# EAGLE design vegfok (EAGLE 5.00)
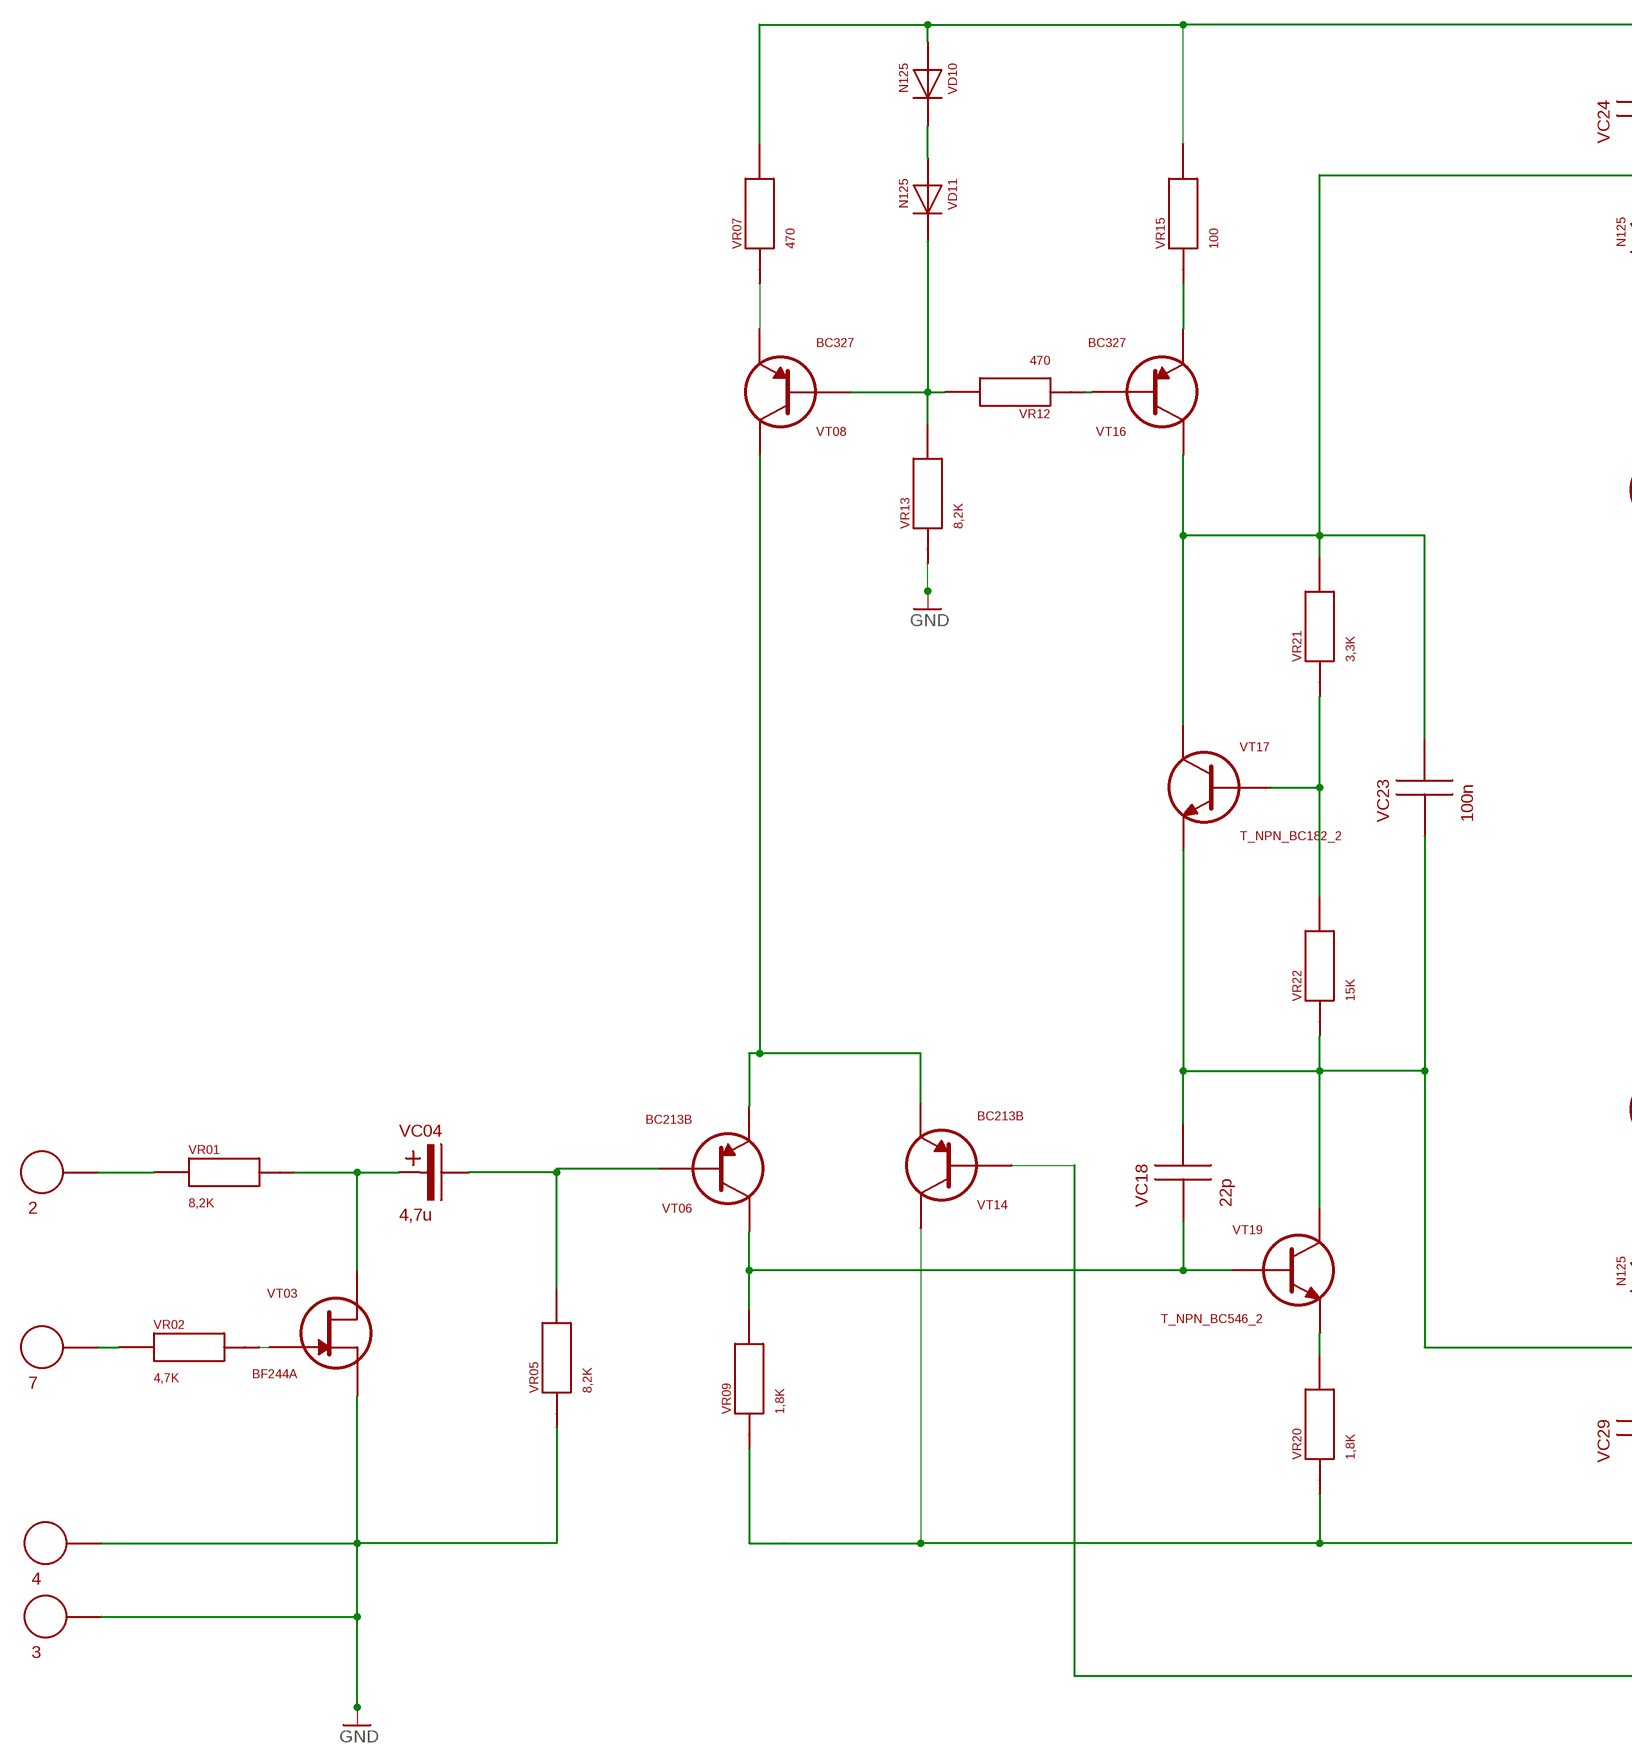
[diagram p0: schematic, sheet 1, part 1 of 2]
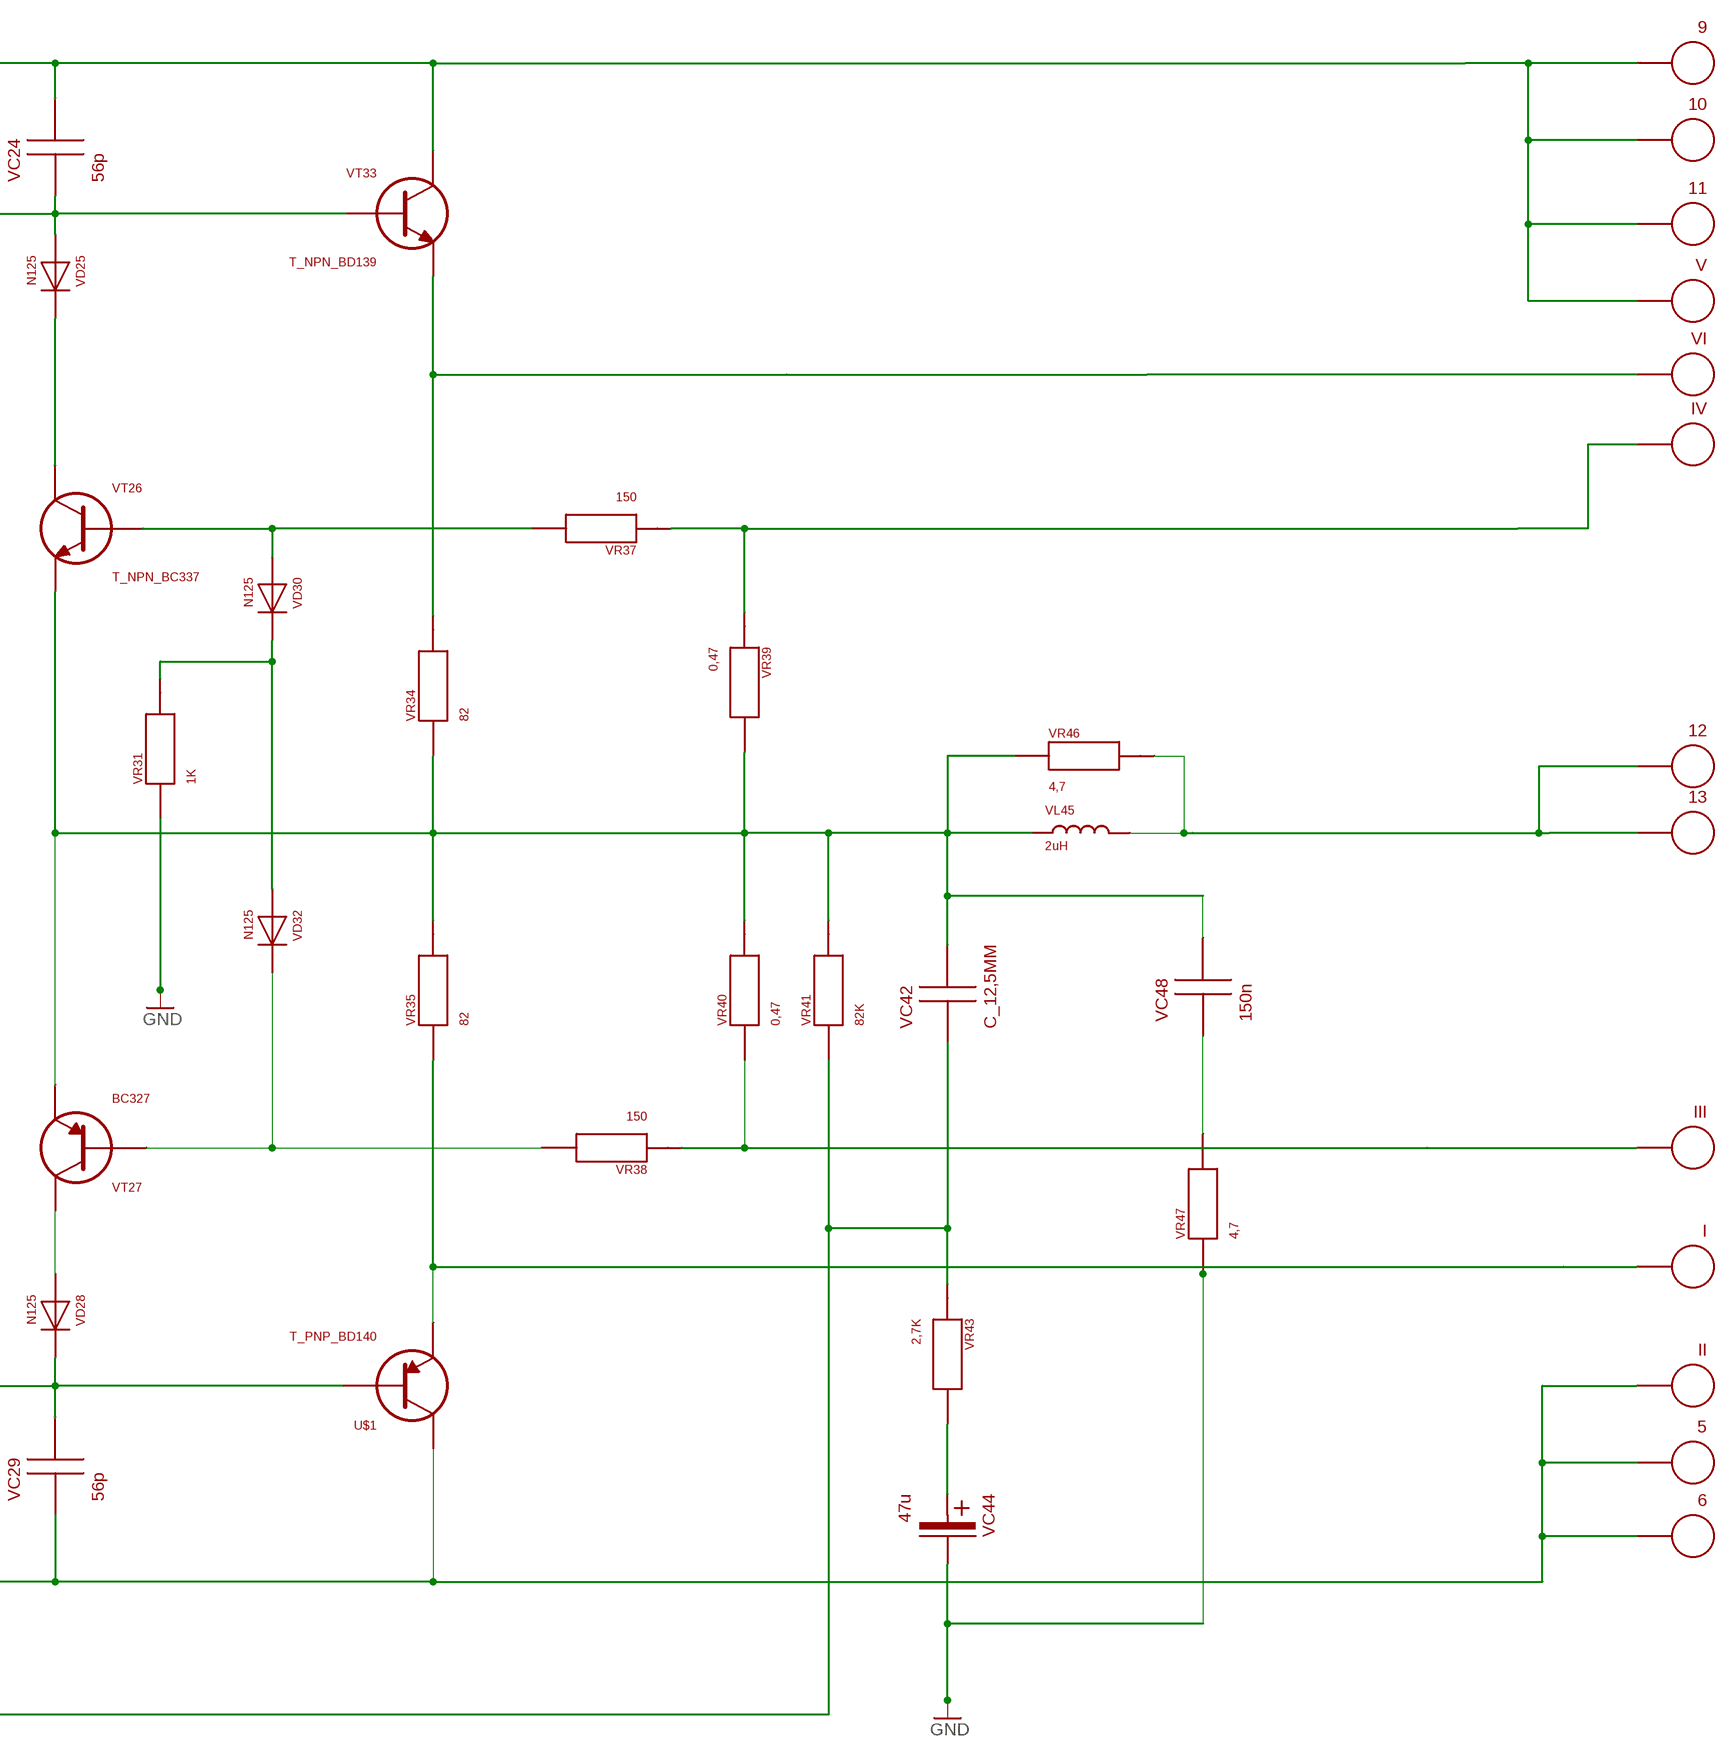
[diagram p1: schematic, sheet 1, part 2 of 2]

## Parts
2  WIREPAD_3-1,2MM  [WIREPAD_3-1,2]
3  WIREPAD_3-1,2MM  [WIREPAD_3-1,2]
4  WIREPAD_3-1,2MM  [WIREPAD_3-1,2]
5  WIREPAD_3-1,2MM  [WIREPAD_3-1,2]
6  WIREPAD_3-1,2MM  [WIREPAD_3-1,2]
7  WIREPAD_3-1,2MM  [WIREPAD_3-1,2]
9  WIREPAD_3-1,2MM  [WIREPAD_3-1,2]
10  WIREPAD_3-1,2MM  [WIREPAD_3-1,2]
11  WIREPAD_3-1,2MM  [WIREPAD_3-1,2]
12  WIREPAD_3-1,2MM  [WIREPAD_3-1,2]
13  WIREPAD_3-1,2MM  [WIREPAD_3-1,2]
I  WIREPAD_3-1,2MM  [WIREPAD_3-1,2]
II  WIREPAD_3-1,2MM  [WIREPAD_3-1,2]
III  WIREPAD_3-1,2MM  [WIREPAD_3-1,2]
IV  WIREPAD_3-1,2MM  [WIREPAD_3-1,2]
U$1  T_PNP_BD140  [TO126]
V  WIREPAD_3-1,2MM  [WIREPAD_3-1,2]
VC04  4,7u  CPOL_17,5MM  [CPOL_17,5]
VC18  22p  C_15MM  [C_15]
VC23  100n  C_15MM  [C_15]
VC24  56p  C_12,5MM  [C_12,5]
VC29  56p  C_15MM  [C_15]
VC42  C_12,5MM  [C_12,5]
VC44  47u  CPOL_22,5MM  [CPOL_22,5]
VC48  150n  C_17,5MM  [C_17,5]
VD10  N125  D_  [D_12,5]
VD11  N125  D_  [D_12,5]
VD25  N125  D_  [D_12,5]
VD28  N125  D_  [D_12,5]
VD30  N125  D_  [D_12,5]
VD32  N125  D_  [D_12,5]
VI  WIREPAD_3-1,2MM  [WIREPAD_3-1,2]
VL45  2uH  L_25MM  [L_25]
VR01  8,2K  R_12,5MM  [R_12,5]
VR02  4,7K  R_12,5MM  [R_12,5]
VR05  8,2K  R_12,5MM  [R_12,5]
VR07  470  R_12,5MM  [R_12,5]
VR09  1,8K  R_12,5MM  [R_12,5]
VR12  470  R_12,5MM  [R_12,5]
VR13  8,2K  R_12,5MM  [R_12,5]
VR15  100  R_12,5MM  [R_12,5]
VR20  1,8K  R_12,5MM  [R_12,5]
VR21  3,3K  R_12,5MM  [R_12,5]
VR22  15K  R_12,5MM  [R_12,5]
VR31  1K  R_12,5MM  [R_12,5]
VR34  82  R_12,5MM  [R_12,5]
VR35  82  R_12,5MM  [R_12,5]
VR37  150  R_12,5MM  [R_12,5]
VR38  150  R_12,5MM  [R_12,5]
VR39  0,47  R_17,5MM  [R_17,5]
VR40  0,47  R_17,5MM  [R_17,5]
VR41  82K  R_12,5MM  [R_12,5]
VR43  2,7K  R_12,5MM  [R_12,5]
VR46  4,7  R_15MM  [R_15]
VR47  4,7  R_15MM  [R_15]
VT03  BF244A  JFET_N_BF244  [TO92]
VT06  BC213B  T_PNP_BC213  [TO92]
VT08  BC327  T_PNP_BC327  [TO92]
VT14  BC213B  T_PNP_BC213  [TO92]
VT16  BC327  T_PNP_BC327  [TO92]
VT17  T_NPN_BC182_2  [TO92_2]
VT19  T_NPN_BC546_2  [TO92_3]
VT26  T_NPN_BC337  [TO92]
VT27  BC327  T_PNP_BC327  [TO92]
VT33  T_NPN_BD139  [TO126]

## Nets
N$1: 2.P$1 VR01.P$1
N$2: VC04.P$1 VR01.P$2 VT03.C(D)
N$3: 7.P$1 VR02.P$1
N$4: VR02.P$2 VT03.B(G)
N$5: VD32.2 VR38.P$2 VT27.B
N$6: VC04.P$2 VR05.P$2 VT06.B
N$7: VC18.P$1 VR09.P$2 VT06.C VT19.B
N$8: 5.P$1 6.P$1 II.P$1 U$1.C VC29.P$1 VR09.P$1 VR20.P$1 VT14.C
N$9: VT06.E VT08.C VT14.E
N$10: 9.P$1 10.P$1 11.P$1 V.P$1 VC24.P$2 VD10.1 VR07.P$2 VR15.P$2 VT33.C
N$11: VR15.P$1 VT16.E
N$12: VR07.P$1 VT08.E
N$13: VD10.2 VD11.1
N$14: VR12.P$1 VT16.B
N$15: VD11.2 VR12.P$2 VR13.P$2 VT08.B
N$17: VC23.P$2 VC24.P$1 VD25.1 VR21.P$2 VT16.C VT17.C VT33.B
N$18: VR21.P$1 VR22.P$2 VT17.B
N$19: U$1.B VC18.P$2 VC23.P$1 VC29.P$2 VD28.2 VR22.P$1 VT17.E VT19.C
N$20: VR20.P$2 VT19.E
N$21: VD25.2 VT26.C
N$22: VC42.P$2 VC48.P$2 VL45.1 VR34.P$1 VR35.P$2 VR39.P$2 VR40.P$2 VR41.P$2 VR46.P$1 VT26.E VT27.E
N$23: VD28.1 VT27.C
N$24: IV.P$1 VR37.P$1 VR39.P$1
N$25: VI.P$1 VR34.P$2 VT33.E
N$26: I.P$1 U$1.E VR35.P$1
N$27: VD30.2 VD32.1 VR31.P$2
N$28: VD30.1 VR37.P$2 VT26.B
N$32: III.P$1 VR38.P$1 VR40.P$1
N$33: VC42.P$1 VR41.P$1 VR43.P$1 VT14.B
N$34: VC44.P$1 VR43.P$2
N$35: VC48.P$1 VR47.P$2
N$36: 12.P$1 13.P$1 VL45.2 VR46.P$2
N$40: 3.P$1 4.P$1 VC44.P$2 VR05.P$1 VR13.P$1 VR31.P$1 VR47.P$1 VT03.E(S) ; supply symbol labelled GND

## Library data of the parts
2-7 9-13 I II III IV V VI = alkatreszek_vidi:WIREPAD_
U$1 VT06 VT08 VT14 VT16 VT27 = alkatreszek_vidi:T_PNP_
VC04 VC44 = alkatreszek_vidi:CPOL_
VC18 VC23 VC24 VC29 VC42 VC48 = alkatreszek_vidi:C_
VD10 VD11 VD25 VD28 VD30 VD32 = alkatreszek_vidi:D_
VL45 = alkatreszek_vidi:L_
VR01 VR02 VR05 VR07 VR09 VR12 VR13 VR15 VR20-VR22 VR31 VR34 VR35 VR37-VR41 VR43 VR46 VR47 = alkatreszek_vidi:R_
VT03 = alkatreszek_vidi:JFET_N_
VT17 VT19 VT26 VT33 = alkatreszek_vidi:T_NPN_

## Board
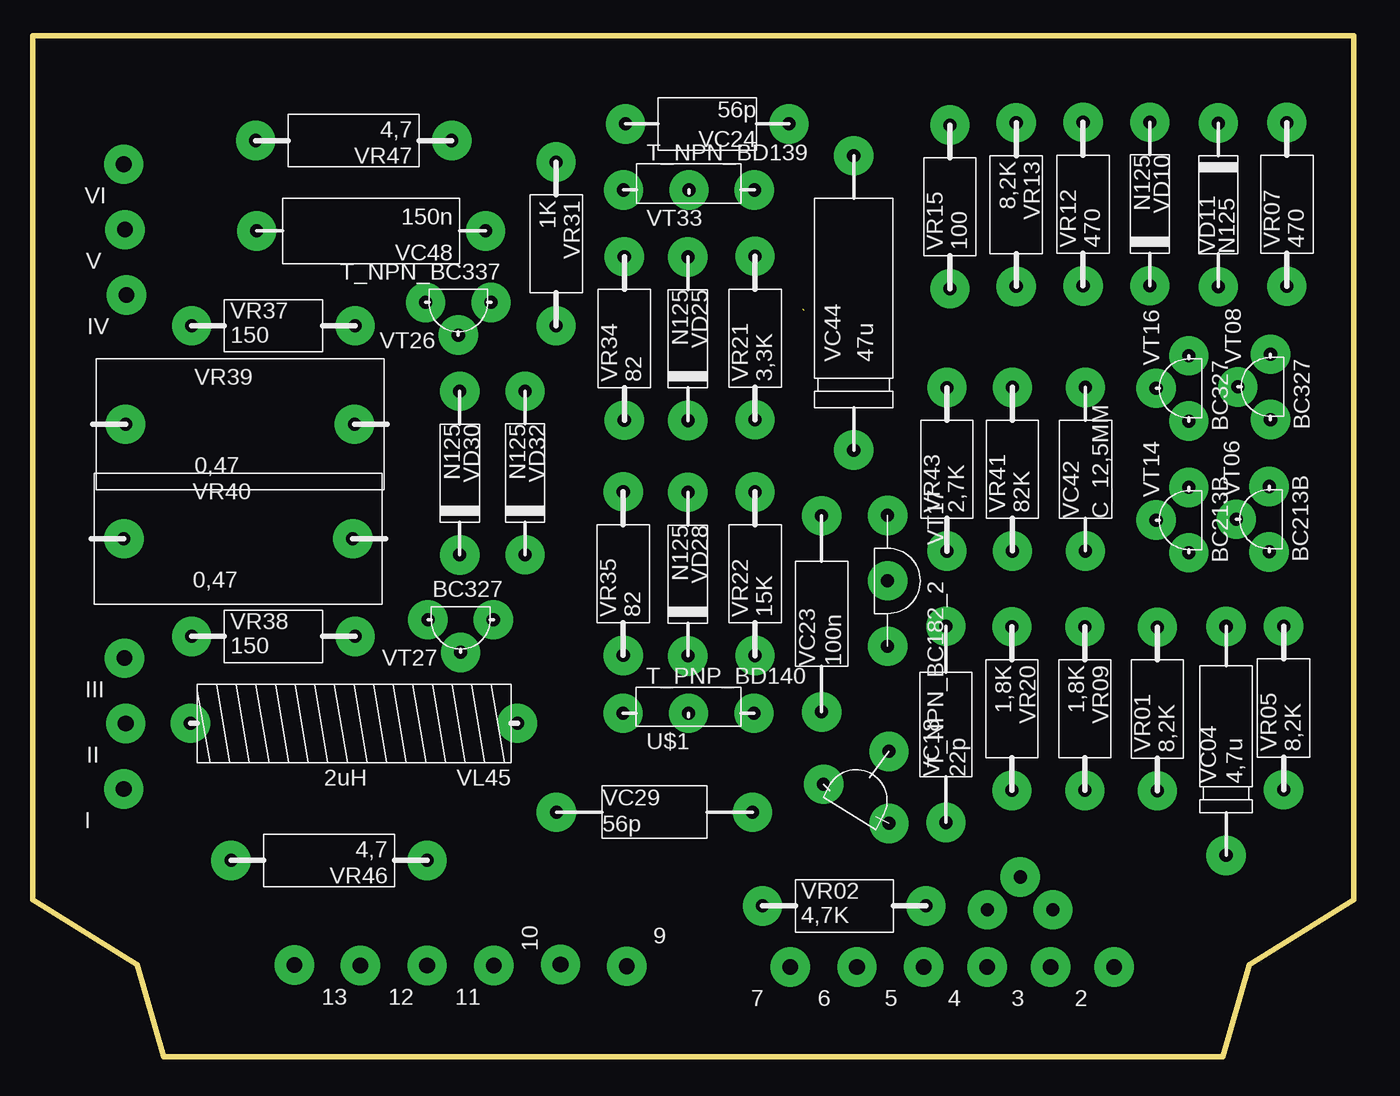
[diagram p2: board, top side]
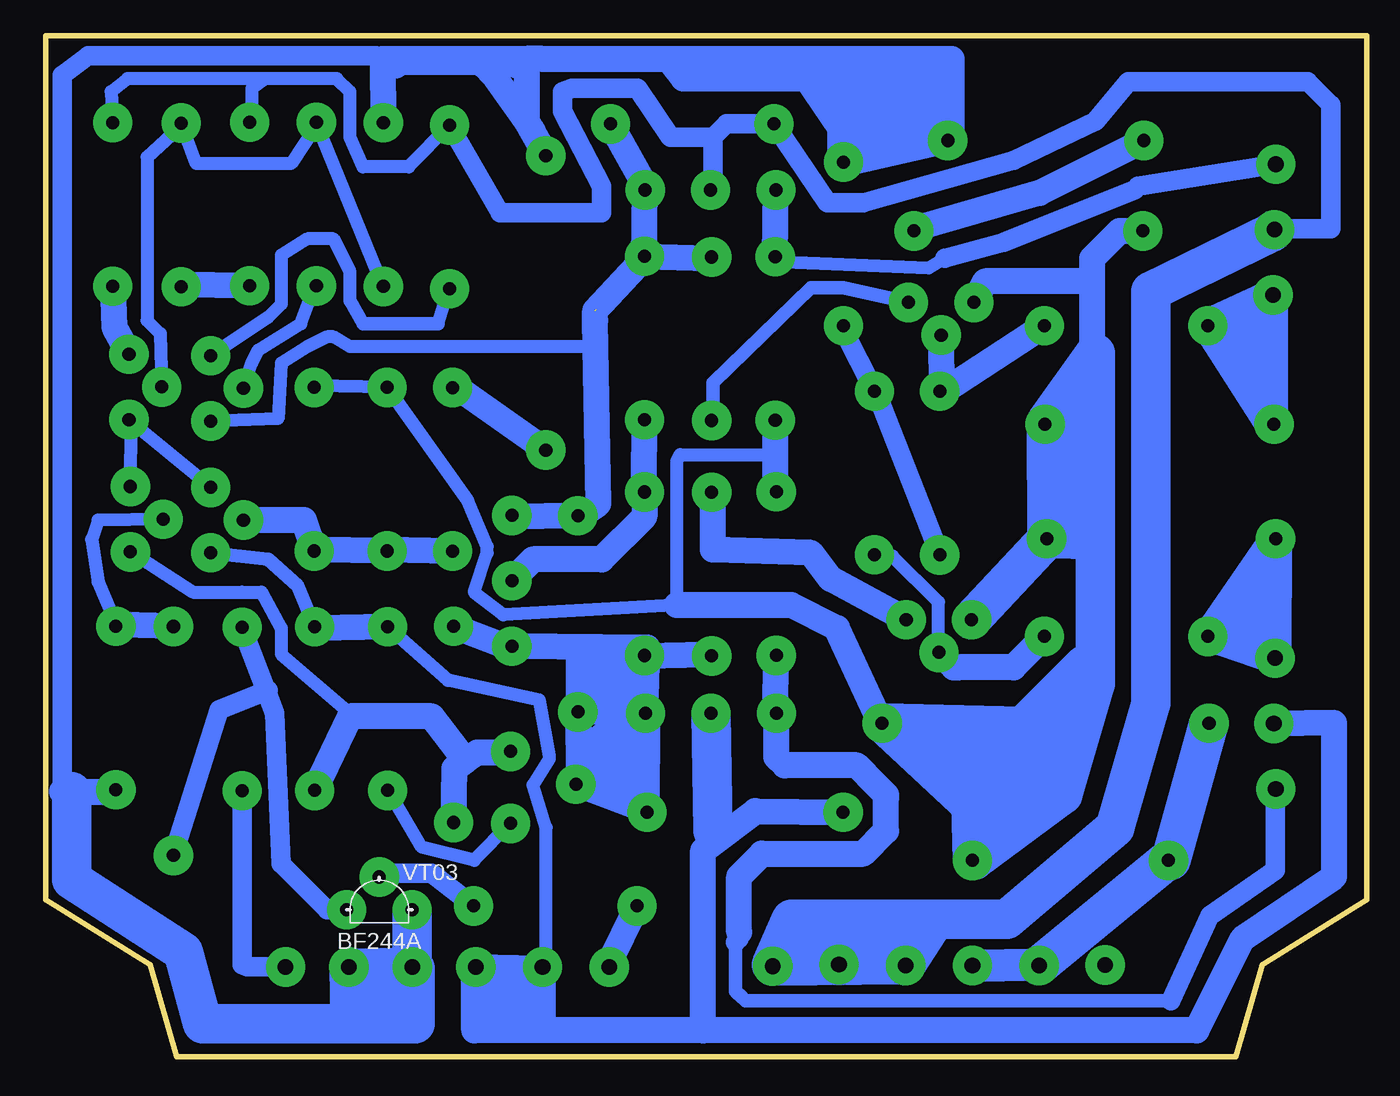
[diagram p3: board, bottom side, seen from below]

Size 101 x 78 mm. Coordinates in mm from the lower left corner, seen from the top.
Outline: 10,0 91,0 93,7 101,12 101,78 0,78 0,12 8,7 10,0
Copper layers (1*16): Top 0.035mm / dielectric 1.5mm / Bottom 0.035mm
Design rules "default *": minimum track width 10mil, minimum drill 24mil, track to track 16mil, track to pad 16mil, pad to pad 8mil, via to via 8mil, smd to smd 8mil, copper to edge 40mil, drill to drill 8mil, minimum pad ring 10mil, minimum via ring 8mil, stop-mask expansion 4mil, vias tented up to drill 0mil, thermal gap 10mil

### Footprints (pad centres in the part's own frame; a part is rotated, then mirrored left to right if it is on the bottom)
WIREPAD_3-1,2 = drill 1.2 pad 3 round: P$1 0,0
TO126 = drill 1 pad 3 round: B 5,0; C 0,0; E -5,0
CPOL_17,5 = drill 1 pad 3 round: P$1 -8.75,0; P$2 8.75,0
C_15 = drill 1 pad 3 round: P$1 -7.5,0; P$2 7.5,0
C_12,5 = drill 1 pad 3 round: P$1 -6.25,0; P$2 6.25,0
CPOL_22,5 = drill 1 pad 3 round: P$1 -11.25,0; P$2 11.25,0
C_17,5 = drill 1 pad 3 round: P$1 -8.75,0; P$2 8.75,0
D_12,5 = drill 1 pad 3 round: 1 -6.25,0; 2 6.25,0
L_25 = drill 1 pad 3 round: 1 -12.5,0; 2 12.5,0
R_12,5 = drill 1 pad 3 round: P$1 -6.25,0; P$2 6.25,0
R_17,5 = drill 1 pad 3 round: P$1 -8.75,0; P$2 8.75,0
R_15 = drill 1 pad 3 round: P$1 -7.5,0; P$2 7.5,0
TO92 = drill 1 pad 3 round: B 0,2.5; C -2.5,0; E 2.5,0
TO92_2 = drill 1 pad 3 round: B 0,0; C -5,0; E 5,0
TO92_3 = drill 1 pad 3 round: B 3,5.5; C -2,3; E 3,0

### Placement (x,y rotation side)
2  82.67,6.85 0 top
3  77.82,6.85 0 top
4  72.97,6.85 0 top
5  68.12,6.85 0 top
6  63.02,6.85 0 top
7  57.92,6.85 0 top
9  45.43,6.9 180 top
10  40.35,7.03 270 top
11  35.26,6.95 0 top
12  30.16,6.95 0 top
13  25.06,6.95 0 top
I  6.96,20.45 0 top
II  7.11,25.45 0 top
III  7.01,30.45 0 top
IV  7.16,58.2 0 top
U$1  50.14,26.23 0 top
V  7.06,63.2 0 top
VC04  91.24,24.12 90 top
VC18  69.82,25.39 90 top
VC23  60.32,33.84 90 top
VC24  51.57,71.28 180 top
VC29  47.54,18.68 0 top
VC42  80.49,44.89 90 top
VC44  62.77,57.6 90 top
VC48  25.87,63.1 180 top
VD10  85.41,65.16 270 top
VD11  90.65,65.09 90 top
VD25  50.09,54.86 270 top
VD28  50.09,36.87 270 top
VD30  32.65,44.59 270 top
VD32  37.65,44.6 270 top
VI  6.96,68.2 0 top
VL45  24.56,25.47 180 top
VR01  85.99,26.56 90 top
VR02  62.05,11.51 0 top
VR05  95.64,26.64 90 top
VR07  95.89,65.13 90 top
VR09  80.44,26.59 270 top
VR12  80.31,65.15 90 top
VR13  75.19,65.11 270 top
VR15  70.13,64.94 90 top
VR20  74.86,26.59 270 top
VR21  55.23,54.91 90 top
VR22  55.23,36.9 90 top
VR31  40.02,62.11 270 top
VR34  45.23,54.88 90 top
VR35  45.15,36.91 90 top
VR37  18.4,55.85 0 top
VR38  18.4,32.11 0 top
VR39  15.85,48.33 0 top
VR40  15.72,39.58 0 top
VR41  74.9,44.89 90 top
VR43  69.9,44.88 90 top
VR46  22.66,14.99 180 top
VR47  24.54,70.01 180 top
VT03  75.5,11.22 0 bottom
VT06  94.53,41.07 90 top
VT08  94.64,51.18 90 top
VT14  88.39,41 90 top
VT16  88.39,51.07 90 top
VT17  65.36,36.36 270 top
VT19  62.47,17.82 0 top
VT26  32.54,57.64 180 top
VT27  32.72,33.39 180 top
VT33  50.17,66.23 0 top

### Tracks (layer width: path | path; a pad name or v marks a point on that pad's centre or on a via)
N$1
  Bottom 1.5: 2.P$1 85.6,6.85 86,7 86,20 86.25,20.25 86.19,20.31 VR01.P$1
N$2
  Bottom 1.5: VT03.C 79.47,11.22 83,14.75 83.5,26.25 84.15,27.94 | VR01.P$2 86,32.75 84.15,27.94 | VC04.P$1 87.75,26.5 84,28 84.15,27.94
N$3
  Bottom 2: 7.P$1 58,7 VR02.P$1
N$4
  Bottom 1.5: VR02.P$2 71.5,14 75.5,14 VT03.B
N$5
  Bottom 1: VT27.B 32.75,30.92 32.75,34.75 36.25,38.25 37.5,38.25 37.55,38.25 VD32.2
  Bottom 2: VR38.P$2 27.01,29.75 31.25,29.75 31.58,29.75 VT27.B
N$6
  Bottom 1: VT06.B 97,41 97.5,39.5 97,36.25 95.5,32.75 VR05.P$2
  Bottom 2: VR05.P$2 95.25,33 VC04.P$2
N$7
  Bottom 1: VT06.C 89.75,35.5 86,35.5 84.5,35.5 83,32.75 83,30.75 77.75,26.25 77.75,26
  Bottom 2: VC18.P$1 69.75,22 68.9,22.61 | 68.9,22.61 68,23.25 65.5,23.25 VT19.B | VR09.P$2 77.75,26 71.5,26 69,22.75 68.9,22.61
N$8
  Bottom 1: VR20.P$1 70.25,28.75 63.25,27.25 62.5,23 62.5,22.75 63.75,20.75 62.75,17.5 62.75,6.75 6.P$1
  Bottom 1.016: VR09.P$1 81.75,36 84,38 88.5,38.5
  Bottom 1.422: 50.31,16.08 50.25,16 50,17.25
  Bottom 2: II.P$1 2.5,25.5 2.5,13.75 9.5,9 13,2 50.75,2 | 50.75,2 68.25,2 68.25,6.75 5.P$1 63.25,6.75 6.P$1 | VC29.P$1 46.75,18.75 50.31,16.08 50.75,15.75 50.75,2.25 50.75,2 | VR09.P$1 80.25,32.75 VR20.P$1 | 88.5,38.5 VT14.C
  Bottom 3: 50,17.25 U$1.C
N$9
  Bottom 1: 94.5,48.5 VT08.C 94.5,48.5 | VT14.E 94.5,48.5 | 94.5,48.5 VT06.E
N$10
  Bottom 1: VR15.P$2 73.25,68 76.75,68 77.75,70.25 77.75,73.75 78.75,74.75 84,74.75 | 84,74.75 84.25,74.75 85.25,74 85.25,71.25 VD10.1 | VR07.P$2 96,73.75 94.75,74.75 84,74.75
  Bottom 1.5: V.P$1 7,63.25 2.75,63.25 2.75,72.75 4.5,74.5 18.25,74.5 20.75,71.5 27,68.5 38.5,65.25 41.25,65.25 VC24.P$2 48.97,71.28 50,70.25 | 50,66.25 VT33.C 50.17,66.08 50.25,66 50,66.25 | 50,70.25 50,66.25 | VR15.P$2 66.25,64.5 58.5,64.5 58.5,66.5 61.5,72.25 61.5,73.75 60.75,74 55.75,74 53.25,70.25 50,70.25
  Bottom 3: 10.P$1 40.5,7 9.P$1 | 35.25,7 11.P$1 | 35.25,7 9.P$1 | 35.25,7 9.P$1 | 35.25,7 33,10.5 32.25,10.5 | 32.25,10.5 27.5,10.5 19.25,17.5 16.5,27 16.5,58.5 7.25,63 V.P$1 | 32.25,10.5 44,10.5 45.5,7 42.5,8.5 36.75,8.75
N$11
  Bottom 1: VT16.E 84,56.5 83,57.5 83,61.25 81,62.5 79,62.5 77.75,60 77.75,57.75 | VR15.P$1 70.25,58.5 71,56
  Bottom 1.016: 77.75,57.75 76.75,56 71,56
N$12
  Bottom 2: VT08.E 95.75,55.75 VR07.P$1
N$13
  Bottom 2: VD11.1 90.75,59 VD10.2
N$14
  Bottom 1: VT16.B 85.25,53 84.75,54 81.5,56 80.5,58.75 VR12.P$1
N$15
  Bottom 1: 80.25,71.25 VR12.P$2 80.25,71.25 | VR13.P$2 80.25,71.25 | 80.25,71.25 82.25,68.25 89.5,68.25 VD11.2 90.5,71.25 93.25,68.75 93.25,56.25 92.25,55.25 VT08.B
N$16  (via drill 1.2 pad 3)
  other vias: 20,7
N$17  (1 unrouted)
  Bottom 1: VT16.C 83.25,48.75 83,53 81,54.25 79.5,55 79,55 77.75,54.25 59.5,54.25 59,57.25 58.88,57.13 | 58.99,56.25 59,56.25
  Bottom 2: VC24.P$1 55,66.25 VT33.B 55.25,61 | 55.25,61 VR21.P$2 50.25,61 VD25.1 | 55.25,61 59,57 58.99,56.25 58.75,42.25 60.25,41.25 VC23.P$2 65.5,41.25 VT17.C
N$18
  Bottom 2: VR21.P$1 55.25,43.75 VR22.P$2 55.23,41.27 58.5,38 63.75,38 65.25,36.5 65.36,36.39 VT17.B
N$19
  Bottom 2: U$1.B 55,26 VC29.P$2 55,18.75 VT19.C | 55,31.25 VR22.P$1 | U$1.B 55,31.25 | VD28.2 50.25,31 50.5,30.75 VR22.P$1 | U$1.B 55,26.25 VC23.P$1 60.25,21.25 | 55,31.25 VR22.P$1 | 55,31.25 VT17.E 65.5,31.25 VC18.P$2
N$20
  Bottom 1: VT19.E 68.25,15 72.25,16 74.75,20.25 VR20.P$2
N$21
  Bottom 1.016: VT26.C 40,58.75 42.5,58.75 50,51.5 50,48.75
  Bottom 1.5: 50,48.75 VD25.2
N$22
  Bottom 1: 45,46.25 46,46 52.5,46 52.75,45.5 52.75,34.5 53,34.5 66,33.75 68.25,35.5 67.25,38.5 67.25,39 68.75,42.5 VR41.P$2 80.5,51.25 VC42.P$2
  Bottom 1.5: 45,46.25 VR34.P$1
  Bottom 2: VC48.P$2 18.9,63.1 21,61 21,59.25 | 20.75,53.75 21,54 21,59.25 | VT26.E 29.18,59.25 21,59.25 | VR35.P$2 45.25,43.5 VR34.P$1 | 52.75,34.5 44,34.5 40.5,32.75 37.25,25.75 VL45.1
  Bottom 3: 37,25.5 VL45.1 | 37,25.5 30.25,19.25 VR46.P$1 30,15 23.25,20 20.75,28.5 20.75,38.75 | VR40.P$2 20.75,39.5 20.75,39.25 20.75,38.75 | VR40.P$2 24.5,39.5 VT27.E | 24.5,48.5 VR39.P$2 | 24.5,48.5 VR40.P$2 | 24.5,48.5 20.75,53.75 20.75,38.75 | 20.75,38.75 22.5,42 22.25,48 | 37,25.5 26.25,25.25 21.5,30 25,22.75 32.25,23 24.75,21 28,18.5 29.25,21
N$23
  Bottom 2: VT27.C 41,36.5 42.5,38.5 50,38.75 50,43.5 VD28.1
N$24
  Bottom 0.406: 7.25,58.25 7.25,58.2 IV.P$1 | VR39.P$1 7.25,48.33 | VR37.P$1 12,55.75
  Bottom 2.5: IV.P$1 arc-238 7.25,58.25 7.25,58.2 | 7.25,48.33 7.25,58.2 | VR37.P$1 12,56 7.25,58.2
N$25
  Bottom 1: 32.25,61 33.5,60.25 45.5,60.75 VR34.P$2
  Bottom 1.5: VI.P$1 17.5,66.5 17.75,66.25 27.75,62.25 32.25,61
  Bottom 2: VR34.P$2 45.25,61.25 VT33.E
N$26
  Bottom 1.016: 48.25,8.75 48.25,5 47.75,4.5 47.5,4.25 15,4.25
  Bottom 1.5: 48,9.5 48,9 48.25,8.75 | 15,4.25 12,10.75 7,14.25 7,20.5 I.P$1
  Bottom 2: VR35.P$1 45.25,26.25 U$1.E 45.14,22.89 44.5,22.25 39,22.25 37.5,20.75 36.75,20 36.75,19.75 36.75,17.25 38.5,15.5 46.25,15.5 48,13.75 48,9.5
N$27
  Bottom 1.5: VD30.2 37.5,50.75 VD32.1 40,55.5 VR31.P$2
N$28
  Bottom 2: 32.5,50.75 VD30.1 32.5,50.75 | VR37.P$2 32.5,50.75 | 32.5,50.75 VT26.B
N$29
  Bottom 2.5: 7.25,48.25 12.25,56 8.5,52.75 8.75,55.25
N$30
  Bottom 2.5: 7,39.5 12,32.25 8.25,33.25 8.5,34.5
N$31
  Bottom 2: 63,6.75 63,2.75 64.25,5.5 64.25,3.25 66,5.75 66,3.5 66.75,3.5 66.75,5.5
N$32
  Bottom 2.5: VR40.P$1 7,30.5 III.P$1 12.25,32.25 VR38.P$1
N$33
  Bottom 2: VR43.P$1 75,38.75 VR41.P$1 80.5,38.75 | 80.5,38.75 VC42.P$1 | 80.5,38.75 81.25,41 85.75,41 VT14.B
N$34
  Bottom 2: VR43.P$2 69.75,51.25 VC44.P$1
N$35
  Bottom 2: VR47.P$2 25,66 34.5,63.25 VC48.P$1
N$36
  Bottom 2.5: 13.P$1 25.25,7 12.P$1 | VR46.P$2 15.25,14.75
  Bottom 3: VL45.2 15,15 VR46.P$2 15.25,15 13.P$1
N$37
  Bottom 2: 40.25,68.25 40.25,71 43.5,75.75 42.75,74.75 52.25,74.75 53.25,76 33.5,75 41,74 40.5,73 33.25,73.75 39.25,71.75 32.75,72.25 39,69.5 32.75,71 39.25,70.25
N$38
  Bottom 2: 65,75.75 64.75,76 74,76 74.25,75.75
N$39
  Bottom 2: 63.75,70.75 66.75,75 67.5,75.75
N$40
  Bottom 1: VR13.P$1 75,76.75 63,76.75 63,76.25
  Bottom 1.5: 75.25,76.25 75.75,76.5 97.75,76.5 99.75,75 99.75,37.25 99.75,20.25
  Bottom 2: VR31.P$1 39.75,68.25 VR47.P$1 31.75,69.75 31.75,76.25 63,76.25 64.25,76.25 64.25,71.5 VC44.P$2 | 75.25,76.25 VR13.P$1 | VR05.P$1 95.5,20.25 99,20.25 99.75,20.25
  Bottom 3: 72.75,6.75 72.75,2.5 79,2.5 | 79,2.5 77.75,2.5 3.P$1 77.5,6.75 4.P$1 73,6.75 VT03.E | 79,2.5 89,2.5 90.5,8 99,13.5 99,19.75 99,20.25 | 79,2.5 75,4.5
N$42
  Bottom 2: 60.25,30.75 60.25,21.75 56.25,20.75 56.25,25.25 58.5,22.5 58.5,24.5 57.75,25 57,22 56.5,30.5 58.5,29.75 58.5,27.75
